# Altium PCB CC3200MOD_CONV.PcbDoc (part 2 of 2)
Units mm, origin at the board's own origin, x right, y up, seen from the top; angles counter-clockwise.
Board outline 40.99 x 49.89 mm, 2 copper layers (Top Layer, Bottom Layer), stack 1.071 mm thick; 81 components, 78 nets, 312 pads, 246 vias.
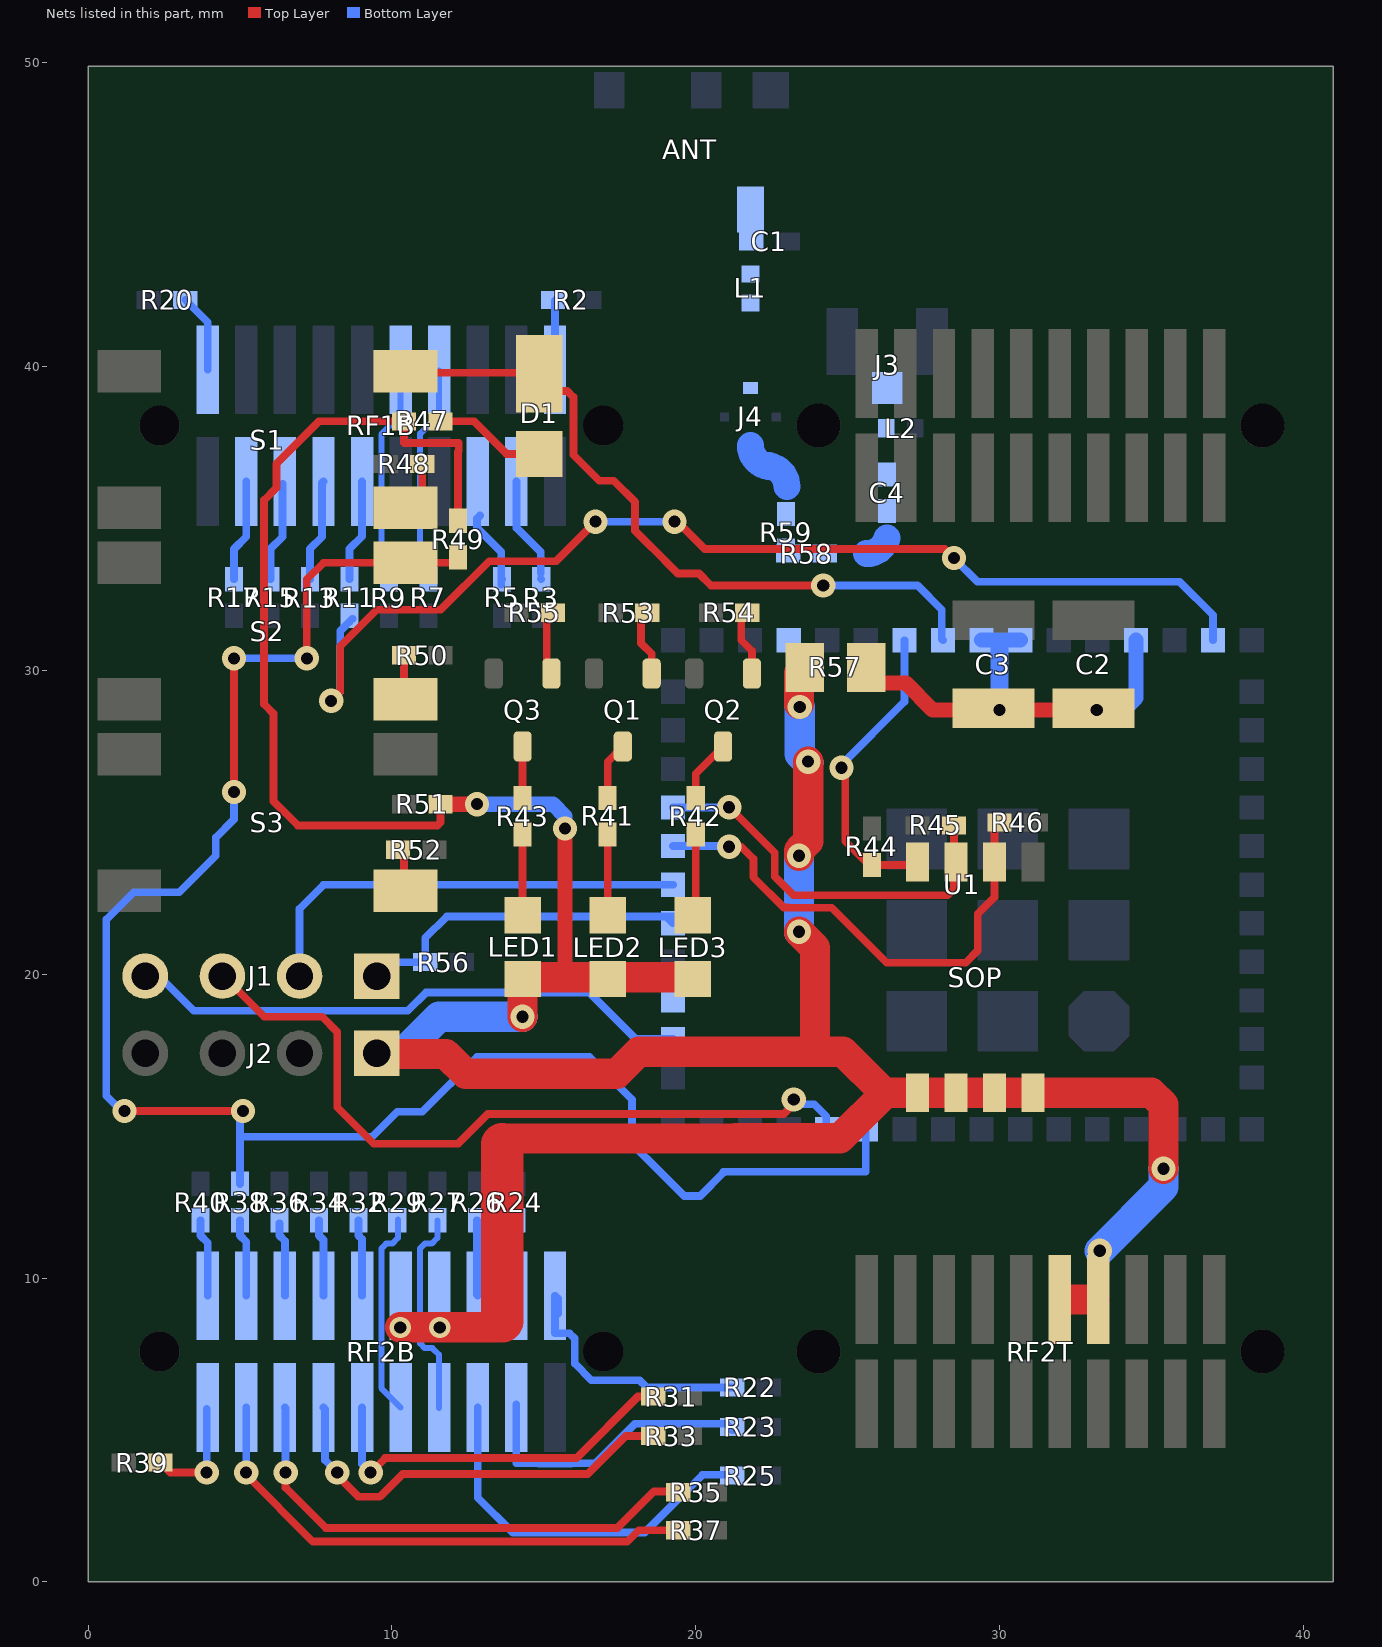
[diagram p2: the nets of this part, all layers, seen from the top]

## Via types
v1: diameter 0.8, hole 0.4, Top Layer to Bottom Layer, tented both sides, 237 vias
v2: diameter 1.27, hole 0.711, Top Layer to Bottom Layer, tented bottom, 7 vias
v3: diameter 0.7, hole 0.4, Top Layer to Bottom Layer, tented both sides, 2 vias

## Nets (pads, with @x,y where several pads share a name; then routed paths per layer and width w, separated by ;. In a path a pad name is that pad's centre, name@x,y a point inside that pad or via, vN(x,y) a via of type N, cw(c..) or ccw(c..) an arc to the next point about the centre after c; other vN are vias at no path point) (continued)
GPIO22: R38.2 R49.2 S2.2 U1.11 | length 60.4
  Top Layer w0.254: v1(1.2,15.5) v1(5.1,15.5) ; v1(4.8,26) v1(4.8,30.4) ; v1(7.2,30.4) 7.2,33 7.75,33.55 S2.2@10.45,33.55 R49.2@12.15,33.55
  Bottom Layer w0.254: v1@1.1,15.5 0.6,16 0.6,21.8 1.5,22.7 3,22.7 4.2,23.9 4.2,24.5 4.8,25.1 v1(4.8,26) ; v1(4.8,30.4) v1(7.2,30.4) ; R38.2@5,13.1 v1@5,15.5 ; 5,14.65 9.35,14.65 10.175,15.475 11,15.475 12.8,17.275 16.507,17.275 17.9,15.882 17.9,14.425 18.8,13.525 ; 18.791,13.534 19.625,12.7 20.149,12.7 20.913,13.463 20.913,13.5 25.6,13.5 U1.11@25.6,14.9
GPIO28: U1.19
GPIO30: R11.1 U1.42 | length 37.7
  Top Layer w0.254: v1(8,29) 8.3,29.3 8.3,30.8 9.5,32 11.6,32 13.2,33.6 15.4,33.6 v1(16.7,34.9) ; v1@19.35,34.95 20.3,34 28.2,34 v1(28.5,33.7)
  Bottom Layer w0.254: v1(8,29) 8.3,29.3 8.3,31.3 R11.1@8.7,31.7 ; v1(16.7,34.9) v1(19.3,34.9) ; v1(28.5,33.7) 29.275,32.925 35.924,32.925 37.03,31.819 U1.42@37.03,31 ; R11.1@8.7,31.7 8.6,31.6 R11.1@8.7,31.7
MCU_RXD: R9.2 RF1B.10 | length 7.3
  Bottom Layer w0.2: R9.2@9.9,33 9.9,33.7 9.65,33.95 9.65,37.775 10.287,38.412 RF1B.10@10.287,39.908
MCU_TXD: R7.2 RF1B.8 | length 7.2
  Bottom Layer w0.2: R7.2@11.2,33 11.2,33.75 10.925,34.025 10.925,37.8 11.55,38.425 RF1B.8@11.55,39.875
NetANT_3: ANT.3 C1.2 L1.2
NetC4_1: C4.1 R58.1 | length 0.9
  Bottom Layer w0.889: 25.625,33.85 ccw(c25.625,34.55) 26.298,34.357
NetC4_2: C4.2 J3.1 L2.2
NetD1_2: D1.2 R47.2 | length 3.9
  Top Layer w0.254: R47.2@11.6,38.2 12.7,38.2 13.775,37.125 D1.2@15.1,37.125
NetJ4_1: J4.1 R59.2 | length 2.2
  Bottom Layer w0.889: J4.1@21.8,37.41 ccw(c22.5,37.41) 22.5,36.71 ; 22.3,36.75 cw(c22.3,36.05) 23,36.05
NetJ4_2: J4.2 L1.1
NetLED1_2: LED1.2 R43.2 | length 2.7
  Top Layer w0.254: R43.2@14.3,24.6 14.3,21.95 LED1.2@14.305,21.945
NetLED2_2: LED2.2 R41.2 | length 2.7
  Top Layer w0.254: R41.2@17.1,24.6 17.1,21.95 LED2.2@17.105,21.945
NetLED3_2: LED3.2 R42.2 | length 2.7
  Top Layer w0.254: LED3.2@19.905,21.945 20,22.041 R42.2@20,24.6
NetQ1_1: Q1.1 R53.2 | length 4.1
  Top Layer w0.254: Q1.1@18.55,29.9 18.55,30.55 18.2,30.9 ; 18.2,30.9 R53.2@18.2,31.9 ; 18.2,30.9 R53.2@18.2,31.9 ; 18.2,30.9 R53.2@18.2,31.9
NetQ1_3: Q1.3 R41.1 | length 1.9
  Top Layer w0.254: R41.1@17.1,25.8 17.1,27 Q1.3@17.6,27.5
NetQ2_1: Q2.1 R54.2 | length 3
  Top Layer w0.254: Q2.1@21.85,29.9 21.85,30.65 21.5,31 ; 21.5,31 21.5,31.9 21.5,31
NetQ2_3: Q2.3 R42.1 | length 2.1
  Top Layer w0.254: R42.1@20,25.8 20,26.6 Q2.3@20.9,27.5
NetQ3_1: Q3.1 R55.2 | length 5.6
  Top Layer w0.254: Q3.1@15.1,30.05 R55.2@15.1,31.9 ; Q3.1@15.1,30.05 R55.2@15.1,31.9 ; Q3.1@15.1,30.05 R55.2@15.1,31.9
NetQ3_3: Q3.3 R43.1 | length 1.7
  Top Layer w0.254: R43.1@14.3,25.8 Q3.3@14.3,27.5
NetR2_2: R2.2 RF1B.2 | length 2.3
  Bottom Layer w0.254: RF1B.2@15.367,39.908 15.367,42.167 R2.2@15.4,42.2
NetR3_2: R3.2 RF1B.3 | length 3.4
  Bottom Layer w0.254: RF1B.3@14.097,36.225 14.1,36.222 14.1,34.7 ; 14.1,34.688 14.1,34.7 ; R3.2@14.897,33.021 R3.2@14.918,33 ; R3.2@14.901,33.202 14.899,33.901 14.1,34.7
NetR5_2: R5.2 RF1B.5 | length 2.9
  Bottom Layer w0.254: RF1B.5@12.9,35.1 12.8,35 12.8,34.7 13.6,33.9 13.6,32.827 13.6,33.027 R5.2@13.627,33
NetR11_2: R11.2 RF1B.11 | length 3.4
  Bottom Layer w0.254: R11.2@8.6,33 8.6,34 9.017,34.417 RF1B.11@9.017,36.225
NetR13_2: R13.2 RF1B.13 | length 3.4
  Bottom Layer w0.254: R13.2@7.3,33 7.3,34 7.7,34.4 7.7,36.178 RF1B.13@7.747,36.225
NetR15_2: R15.2 RF1B.15 | length 3.3
  Bottom Layer w0.254: R15.2@6,33 6,34 6.4,34.4 RF1B.15@6.4,36.148
NetR17_2: R17.2 RF1B.17 | length 3.4
  Bottom Layer w0.254: R17.2@4.8,33 4.8,34 5.207,34.407 RF1B.17@5.207,36.225
NetR20_2: R20.2 RF1B.20 | length 2.6
  Bottom Layer w0.254: R20.2@3.2,42.2 3.937,41.463 RF1B.20@3.937,39.908
NetR22_2: R22.2 RF2B.2 | length 8.8
  Bottom Layer w0.254: RF2B.2@15.367,9.422 15.367,8.183 15.842,8.183 16.015,8.01 16.015,7.191 16.565,6.64 18.148,6.64 18.389,6.4 R22.2@21.2,6.4 ; RF2B.2@15.464,8.836 RF2B.2@15.464,9.325
NetR23_2: R23.2 RF2B.3 | length 9.7
  Bottom Layer w0.254: RF2B.3@14.097,5.839 14.097,3.903 14.1,3.9 14.838,3.9 14.841,3.897 15.893,3.897 15.896,3.9 16.7,3.9 18,5.2 21,5.2 R23.2@21.2,5
NetR24_1: R24.1 RF2B.4 | length 2.5
  Bottom Layer w0.254: RF2B.4@14.097,9.422 14.1,9.425 R24.1@14.1,11.9
NetR25_2: R25.2 RF2B.5 | length 12.4
  Bottom Layer w0.254: RF2B.5@12.827,5.739 12.827,2.773 13.975,1.625 18.325,1.625 20.225,3.525 R25.2@21.025,3.525
NetR26_1: R26.1 RF2B.6 | length 2.5
  Bottom Layer w0.254: R26.1@12.8,11.9 12.8,9.448 RF2B.6@12.827,9.422
NetR27_2: R27.2 RF2B.7 | length 7
  Bottom Layer w0.2: R27.2@11.5,11.9 11.5,11.325 11.309,11.134 11.084,11.134 10.925,10.975 10.925,7.85 11.081,7.694 11.331,7.694 11.55,7.475 RF2B.7@11.55,5.725
NetR29_2: R29.2 RF2B.9 | length 6.8
  Bottom Layer w0.2: R29.2@10.2,11.925 10.2,11.325 10.009,11.134 9.814,11.134 9.65,10.97 9.65,6.376 RF2B.9@10.287,5.739
NetR31_2: R31.2 RF2B.11 | length 12.6
  Top Layer w0.254: v1(9.3,3.6) 9.775,4.075 16.075,4.075 18.1,6.1 R31.2@18.6,6.1
  Bottom Layer w0.254: RF2B.11@9.017,5.739 9.017,3.883 v1(9.3,3.6)
NetR32_1: R32.1 RF2B.12 | length 2.5
  Bottom Layer w0.254: R32.1@8.9,11.9 8.9,11.4 9.017,11.283 RF2B.12@9.017,9.422
NetR33_2: R33.2 RF2B.13 | length 14.1
  Top Layer w0.254: v1@8.3,3.6 v1(8.2,3.6) 8.2,3.5 8.9,2.8 9.6,2.8 9.619,2.819 9.624,2.819 10.355,3.55 16.45,3.55 17.7,4.8 R33.2@18.6,4.8
  Bottom Layer w0.254: RF2B.13@7.747,5.739 7.8,5.685 7.8,4 v1(8.2,3.6) v1@8.3,3.6
NetR34_1: R34.1 RF2B.14 | length 2.5
  Bottom Layer w0.254: R34.1@7.6,11.9 7.6,11.4 7.747,11.253 RF2B.14@7.747,9.422
NetR35_2: R35.2 RF2B.15 | length 17.1
  Top Layer w0.254: v1@6.3,3.6 v1(6.5,3.6) 6.5,3.1 7.825,1.775 17.425,1.775 18.625,2.975 R35.2@19.5,2.975
  Bottom Layer w0.254: v1@6.3,3.6 v1(6.5,3.6) 6.5,5.716 RF2B.15@6.477,5.739
NetR36_1: R36.1 RF2B.16 | length 2.5
  Bottom Layer w0.254: R36.1@6.3,11.8 6.3,11.4 6.477,11.223 RF2B.16@6.477,9.422
NetR37_2: R37.2 RF2B.17 | length 17.5
  Top Layer w0.254: v1(5.2,3.6) 5.2,3.525 7.4,1.325 17.75,1.325 18.125,1.7 R37.2@19.4,1.7
  Bottom Layer w0.254: v1(5.2,3.6) 5.2,5.732 RF2B.17@5.207,5.739
NetR38_1: R38.1 RF2B.18 | length 2.6
  Bottom Layer w0.254: R38.1@5,11.9 5,11.4 5.207,11.193 RF2B.18@5.207,9.422
NetR39_2: R39.2 RF2B.19 | length 3.8
  Top Layer w0.254: R39.2@2.375,3.925 2.7,3.6 v1(3.9,3.6)
  Bottom Layer w0.254: v1(3.9,3.6) RF2B.19@3.9,5.701
NetR40_1: R40.1 RF2B.20 | length 2.6
  Bottom Layer w0.254: R40.1@3.7,11.9 3.7,11.4 3.937,11.163 RF2B.20@3.937,9.422
NetR48_1: R48.1 S1.4 | length 1.9
  Top Layer w0.254: S1.4@10.4,35.6 S1.4@10.55,35.45 ; S1.4@10.45,35.35 S1.4@10.55,35.45 ; R48.1@11,36.8 11,35.9 S1.4@10.55,35.45
NetR50_1: R50.1 S2.4 | length 2.3
  Top Layer w0.254: R50.1@10.4,30.5 S2.4@10.4,29.3 ; S2.4@10.4,29.3 10.55,29.15 S2.4@10.65,29.05 ; S2.4@10.4,29.3 S2.4@10.65,29.05 ; S2.4@10.4,29.3 S2.4@10.65,29.05
NetR52_1: R52.1 S3.4 | length 2.2
  Top Layer w0.254: R52.1@10.4,24.1 S3.4@10.4,23 ; S3.4@10.4,23 10.55,22.85 S3.4@10.65,22.75 ; S3.4@10.4,23 S3.4@10.65,22.75 ; S3.4@10.4,23 S3.4@10.65,22.75
NRESET: D1.1 S1.2 U1.35 | length 23.7
  Top Layer w0.254: S1.2@10.65,39.85 10.7,39.8 14.625,39.8 D1.1@14.754,39.671 ; D1.1@14.85,39.767 15.417,39.2 15.775,39.2 15.975,39 15.975,37.1 16.825,36.25 17.3,36.25 18,35.55 18,34.6 18.543,34.057 ; 18.5,34.1 19.408,33.192 20.108,33.192 20.5,32.8 24.4,32.8 24.4,32.6 v1(24.2,32.8)
  Bottom Layer w0.254: 24.6,32.8 27.3,32.8 28.1,32 28.1,31.04 U1.35@28.14,31
RF_BG: R58.2 R59.1 U1.31
SOP0: R44.2 SOP.8 U1.34 | length 10.2
  Top Layer w0.254: v1@24.8,26.6 24.925,26.475 24.925,24.375 25.7,23.6 26.1,23.6 ; R44.2@26,23.6 27.2,23.6 SOP.8@27.295,23.695
  Bottom Layer w0.254: v1(24.8,26.8) 24.8,26.9 26.87,28.97 U1.34@26.87,31
SOP1: R45.2 SOP.7 U1.24 | length 13.2
  Top Layer w0.254: v1(21.1,25.5) 22.6,24 22.6,23.218 23.218,22.6 28.3,22.6 28.5,22.8 R45.2@28.5,25
  Bottom Layer w0.254: U1.24@19.25,25.49 v1@21.09,25.49
SOP2: R46.2 SOP.6 U1.23 | length 16.6
  Top Layer w0.254: v1(21.1,24.2) 21.5,24.2 21.9,23.8 21.9,23.2 22.9,22.2 23.044,22.2 23.05,22.194 24.474,22.194 26.284,20.384 28.884,20.384 29.284,20.784 29.284,21.984 29.835,22.535 SOP.6@29.835,23.695 29.835,24.965 R46.2@29.8,25
  Bottom Layer w0.254: U1.23@19.25,24.22 v1@21.08,24.22
TCK: J1.1 R56.2 U1.21 | length 11.7
  Bottom Layer w0.254: J1.1@9.5,20.4 R56.2@11.1,20.4 11.1,21.2 11.8,21.9 U1.21@19.3,21.9 ; U1.21@19.25,21.68 U1.21@19.03,21.9 ; U1.21@19.03,21.9 19.25,21.9 U1.21@19.3,21.9 ; U1.21@19.03,21.9 U1.21@19.3,21.9
TDI: J1.3 U1.12 | length 25.5
  Top Layer w0.254: J1.3@4.42,20.4 4.42,19.98 5.8,18.6 7.7,18.6 8.2,18.1 8.2,15.625 9.4,14.425 12.175,14.425 13.15,15.4 22.9,15.4 23.225,15.725 v1(23.225,15.875)
  Bottom Layer w0.254: v1(23.225,15.875) 23.375,15.725 23.9,15.725 24.3,15.325 U1.12@24.3,14.93 ; U1.12@24.3,15 U1.12@24.3,14.93 ; U1.12@24.33,14.9 U1.12@24.3,14.93
TDO: J1.4 U1.18 | length 18.9
  Bottom Layer w0.254: J1.4@1.88,20.4 3.48,18.8 10.525,18.8 11.125,19.4 16.5,19.4 18.03,17.87 U1.18@19.25,17.87
TMS: J1.2 U1.22 | length 16.1
  Bottom Layer w0.254: U1.22@19.25,22.95 7.75,22.95 6.96,22.16 ; 6.96,22.16 6.96,20.4 6.96,22.16
VCC: C2.1 C3.1 R57.2 U1.36 U1.37 U1.40 | length 16.8
  Top Layer w0.5: R57.2@25.5,29.584 26.916,29.584 27.8,28.7 v1(30,28.7) ; 28.1,28.7 v1(30,28.7) ; v1(33.2,28.7) v1(30,28.7)
  Bottom Layer w0.5: U1.36@29.41,31 U1.37@30.68,31 ; v1(33.2,28.7) 34.1,28.7 34.49,29.09 U1.40@34.49,31
  Bottom Layer w0.58: v1(30,28.7) 30,30.95
VCC_BRD: J2.1 LED1.1 LED2.1 LED3.1 R47.1 R49.1 R51.1 R57.1 RF2B.8 RF2B.10 RF2T.7 RF2T.9 SOP.1 SOP.2 SOP.3 SOP.4 | length 118.5
  Top Layer w0.254: R51.1@11.6,25.6 11.6,25 11.5,24.9 6.9,24.9 6.1,25.7 6.1,28.582 5.792,28.89 5.792,35.61 6.2,36.018 6.2,36.8 7.6,38.2 R47.1@10.4,38.2 10.4,37.5 10.409,37.491 12.2,37.491 12.2,37.225 12.175,37.2 12.175,36.205 R49.1@12.175,34.925 ; LED1.1@14.3,19.841 LED1.1@14.305,19.845 LED1.1@14.359,19.9 ; LED2.1@17.05,19.9 LED2.1@17.105,19.845 ; LED3.1@19.85,19.9 LED3.1@19.905,19.845 LED3.1@19.959,19.9
  Top Layer w0.5: J2.1@9.5,17.35 J2.1@9.525,17.375 ; R51.1@11.6,25.6 v1(12.8,25.6) ; 15.7,19.9 v1(15.7,24.8)
  Top Layer w1: J2.1@9.525,17.375 11.775,17.375 12.425,16.725 17.4,16.725 18.125,17.45 24.85,17.45 26.2,16.1 32.9,16.1 ; v3(10.275,8.375) v3(11.575,8.375) 13.425,8.375 13.625,8.575 ; 13.625,14.4 13.821,14.596 ; 13.721,14.596 21.306,14.596 21.311,14.6 24.75,14.6 26.25,16.1 ; v1(14.3,18.6) LED1.1@14.3,19.841 ; LED1.1@14.359,19.9 15.7,19.9 LED2.1@17.05,19.9 ; LED2.1@17.505,19.9 LED3.1@19.85,19.9 ; v1(23.4,21.4) 23.925,20.875 23.925,17.5 ; v1(23.4,23.9) 23.4,24.075 23.7,24.375 v1(23.7,27) ; v1@23.4,28.9 R57.1@23.4,29.916 ; RF2T.9@32.125,9.295 RF2T.7@33.125,9.295 ; 33,16.1 35,16.1 35.4,15.7 v1(35.4,13.6)
  Top Layer w1.4: 13.625,8.575 13.625,14.4
  Bottom Layer w0.254: v1@23.7,26.95 v1(23.7,27)
  Bottom Layer w0.5: v1(12.8,25.6) 15.3,25.6 15.7,25.2 v1(15.7,24.8)
  Bottom Layer w1: J2.1@9.525,17.425 9.575,17.375 10.325,17.375 11.55,18.6 v1(14.3,18.6) ; v1(23.4,21.4) v1(23.4,23.9) ; v1(23.425,28.8) 23.425,27.25 v1@23.7,26.975 ; v1(33.3,10.9) 35.4,13 v1(35.4,13.6)
pads on no net: Logo1.0 R3.1 R5.1 R13.1 R15.1 R17.1 R36.2 RF1B.1 RF1B.4 RF1B.6 RF1B.7 RF1B.9 RF1B.12 RF1B.14 RF1B.16 RF1B.18 RF1B.19 RF1B.21 RF1B.22 RF1T. RF1T.2 RF1T.3 RF1T.4 RF1T.5 RF1T.6 RF1T.8 RF1T.10 RF1T.11 RF1T.12 RF1T.13 RF1T.14 RF1T.15 RF1T.16 RF1T.17 RF1T.18 RF1T.20 RF2B.21 RF2B.22 RF2T. RF2T.1 RF2T.3 RF2T.4 RF2T.5 RF2T.6 RF2T.8 RF2T.10 RF2T.11 RF2T.12 RF2T.13 RF2T.14 RF2T.15 RF2T.16 RF2T.17 RF2T.18 RF2T.19 S1.1 S1.3 S2.1 S2.3 S3.1 S3.3 U1.13 U1.14 U1.15 U1.17 U1.20 U1.25 U1.26 U1.29 U1.33 U1.39 U1.41 U1.45

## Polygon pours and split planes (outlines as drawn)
DGND on Top Layer "Top Layer-No Net" (solid, remove dead copper, pour order 6): 0,49.9 41,49.9 41,0 0,0 0,49.9
DGND on Bottom Layer "Bottom Layer-No Net" (solid, remove dead copper, pour order 10): 40.998,49.843 -0.002,49.843 -0.002,0.043 40.998,0.043 40.998,49.843

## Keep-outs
Keep-Out Layer:
  lines w0.254: -0.127,50.021 -0.127,0 ; 0,50.021 41.115,50.021 41.115,-0.127 0,-0.127 ; -0.127,0 ccw(c0,0) 0,-0.127 ; -0.127,0 ccw(c0,0) 0,-0.127 ; -0.127,0 ccw(c0,0) 0,-0.127 ; -0.127,0 ccw(c0,0) 0,-0.127 ; -0.127,0 ccw(c0,0) 0,-0.127 ; -0.127,0 ccw(c0,0) 0,-0.127 ; 116.53,78.957 cw(c116.53,78.83) 116.657,78.83 ; 116.53,78.957 cw(c116.53,78.83) 116.657,78.83 ; 116.53,78.957 cw(c116.53,78.83) 116.657,78.83 ; 116.53,78.957 cw(c116.53,78.83) 116.657,78.83 ; 116.53,78.957 cw(c116.53,78.83) 116.657,78.83 ; 116.53,78.957 cw(c116.53,78.83) 116.657,78.83
  text ".Layer_Name" at 14.656,-21.806 h1.52

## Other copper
Top Layer:
  text ".PRJ_Number" at 41.75,39.33 h1
  text ".Layer_Name" at 14.656,-21.806 h1.52
Bottom Layer:
  rectangle net NetJ4_2: 21.35,39.1 22.25,42.375
  rectangle net NetC4_1: 25.85,34.4 26.75,35.65
  region net NetC4_1: 25.625,33.406 25.625,34.295 23.762,34.295 23.762,33.406
  rectangle net NetC4_2: 25.85,36.05 26.75,39.8
  rectangle net NetANT_3: 21.35,42.775 22.25,45.925
  rectangle net NetJ4_1: 22.55,34.75 23.45,36.1
  rectangle net NetC4_1: 25.85,35.5 26.75,39.25
  rectangle net RF_BG: 22.55,30.6 23.45,34.525
  text ".PRJ_Number" at 41.75,37.457 h1
  text ".VersionControl_RevNumber" at 98.831,4.559 h1.52
  text "SVN:" at 105.918,4.559 h1.52
  text ".Layer_Name" at 14.656,-21.806 h1.52

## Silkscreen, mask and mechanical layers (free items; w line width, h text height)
Top Overlay:
  text ".PRJ_Number" at 41.75,44.95 h1
  text "SOP0" at 27,14.3 h0.8 r270
  text "SOP1" at 28.2,14.3 h0.8 r270
  text "SOP2" at 29.5,14.3 h0.8 r270
  text "MODE" at 30.8,14.3 h0.8 r270
  text "J1:" at 3.5,6.2 h0.8
  text "TDO" at 5.6,6.2 h0.8
  text "TDI" at 8.1,6.2 h0.8
  text "TMS" at 10.6,6.2 h0.8
  text "TCK" at 13.2,6.2 h0.8
  text "J2:" at 3.4,4.5 h0.8
  text "VSS" at 5.575,4.3 h0.8
  text "TXD" at 8.075,4.3 h0.8
  text "RXD" at 10.675,4.3 h0.8
  text "VDD" at 13.2,4.3 h0.8
  text "©" at 25,1.1 h2.67
  text ".CopyrightYear" at 27.39,1.1 h1.52
  text "TI" at 36.1,1.1 h1.52
  text ".Layer_Name" at 14.656,-21.806 h1.52
Bottom Overlay:
  text "*" at 16.025,40.425 h1.02
  text ".PRJ_Number" at 41.75,31.837 h1
  text "UL94V-0" at 14.575,23.3 h1.52
  text "*" at 16.05,10 h1.02
  text ".PCB_Rev" at 20.55,9.475 h1
  text ".PRJ_Number" at 40.6,9.425 h1
  text ".Layer_Name" at 14.656,-21.806 h1.52
Top Paste:
  text ".PRJ_Number" at 41.75,41.204 h1
  text ".Layer_Name" at 14.656,-21.806 h1.52
Bottom Paste:
  text ".PRJ_Number" at 41.75,35.584 h1
  text ".Layer_Name" at 14.656,-21.806 h1.52
Top Solder:
  text ".PRJ_Number" at 41.75,43.077 h1
  text ".Layer_Name" at 14.656,-21.806 h1.52
  text ".Layer_Name" at 14.656,-21.806 h1.52
Bottom Solder:
  text ".PRJ_Number" at 41.75,33.711 h1
  text ".Layer_Name" at 14.656,-21.806 h1.52
Drill Guide:
  text ".PRJ_Number" at 41.75,22.471 h1
  text ".Layer_Name" at 14.656,-21.806 h1.52
M1 Board Outline:
  lines w0.254: 40.988,10 40.988,0 0,0 0,49.894 40.988,49.894 40.988,10.012
  text ".PRJ_Number" at 41.75,29.964 h1
  text ".Layer_Name" at 14.656,-21.806 h1.52
M2 Board Dimensions:
  rectangle: 0,-7.252 3.175,-4.077
  rectangle: 3.175,-10.427 12.7,-7.252
  lines w0.178: 0,-7.252 25.4,-7.252 ; 3.175,-10.427 3.175,-4.077 ; 6.35,-10.427 6.35,-4.077 ; 12.7,-10.427 12.7,-4.077 ; 19.05,-10.427 19.05,-4.077 ; 0,-10.427 25.4,-10.427 25.4,-4.077 0,-4.077 0,-10.427
  text ".PRJ_Number" at 41.75,28.091 h1
  text ".Layer_Name" at 14.656,-21.806 h1.52
M3 3D STEP Top:
  text ".Layer_Name" at 14.656,-21.806 h1.52
M4 3D STEP Bottom:
  text ".Layer_Name" at 14.656,-21.806 h1.52
M5 Assembly Top:
  lines w0.254: -7.417,-23.626 160.223,-23.626 ; -7.417,-18.462 160.274,-18.462 ; -7.417,-13.297 -7.417,-28.791 94.31,-28.791 160.274,-28.791 160.274,-13.297 -7.404,-13.297 -7.404,-28.791 32.614,-28.791 ; 55.194,-28.791 55.194,-13.297 ; 87.376,-18.462 87.376,-13.297 ; 108.712,-18.462 108.712,-13.297 ; 124.511,-28.956 124.511,-23.804
  text ".PRJ_Number" at 41.75,26.218 h1
  text "COMPONENTS MARKED 'DNP' SHOULD NOT BE POPULATED." at 29.299,-8.09 h1.52
  text "ASSEMBLY VARIANT:" at 29.286,-11.024 h1.52
  text ".VariantName" at 55.601,-11.024 h1.52
  text "PCB VIEWED FROM TOP SIDE" at -5.804,-16.654 h1.52
  text "BOARD #:" at 57.099,-16.654 h1.52
  text ".PRJ_Number" at 70.955,-16.654 h1.52
  text "REV:" at 92.405,-16.654 h1.52
  text ".PCB_Rev" at 99.809,-16.654 h1.52
  text "SVN REV:" at 113.69,-16.654 h1.52
  text ".VersionControl_RevNumber" at 126.543,-16.654 h1.52
  text "IGNORE ->" at -5.804,-21.806 h1.52
  text "PLOT NAME =" at -5.804,-27.034 h1.52
  text ".plot_File_Name" at 14.656,-27.034 h1.52
  text "GENERATED    :" at 57.15,-27.034 h1.52
  text ".Print_Date" at 79.235,-27.034 h1.52
  text ".Print_Time" at 97.752,-27.034 h1.52
  text "TEXAS INSTRUMENTS" at 129.87,-27.034 h1.52
M6 Assembly Bottom:
  lines w0.254: -7.429,-18.474 160.261,-18.474 ; -7.379,-23.639 160.261,-23.639 ; 28.334,-28.969 28.334,-23.817 ; 44.133,-18.474 44.133,-13.31 ; 65.468,-18.474 65.468,-13.31 ; 97.65,-28.804 97.65,-13.31 ; 120.231,-28.804 160.249,-28.804 160.249,-13.31 -7.429,-13.31 -7.429,-28.804 58.534,-28.804 160.261,-28.804 160.261,-13.31
  text ".PRJ_Number" at 41.75,24.345 h1
  text "COMPONENTS MARKED 'DNP' SHOULD NOT BE POPULATED." at 154.991,-8.077 h1.52
  text ".VariantName" at 128.473,-11.024 h1.52
  text "ASSEMBLY VARIANT:" at 154.864,-11.024 h1.52
  text ".VersionControl_RevNumber" at 26.302,-16.667 h1.52
  text "SVN REV:" at 39.154,-16.667 h1.52
  text ".PCB_Rev" at 53.035,-16.667 h1.52
  text "REV:" at 60.439,-16.667 h1.52
  text ".PRJ_Number" at 81.89,-16.667 h1.52
  text "BOARD #:" at 95.745,-16.667 h1.52
  text "PCB VIEWED FROM BOTTOM SIDE" at 158.648,-16.667 h1.52
  text "IGNORE ->" at 64.715,-21.806 h1.52
  text "TEXAS INSTRUMENTS" at 22.974,-27.047 h1.52
  text ".Print_Time" at 55.093,-27.047 h1.52
  text ".Print_Date" at 73.609,-27.047 h1.52
  text "GENERATED    :" at 95.694,-27.047 h1.52
  text ".plot_File_Name" at 138.189,-27.047 h1.52
  text "PLOT NAME =" at 158.648,-27.047 h1.52
M9 Title Sheet:
  drawing of 57 lines, arcs and shapes, not listed
  text "1" at 18.792,204.127 h1.78
  text "2" at 82.182,204.127 h1.78
  text "3" at 145.411,204.127 h1.78
  text "4" at 209.08,204.127 h1.78
  text "5" at 272.555,204.127 h1.78
  text "6" at 336.182,204.127 h1.78
  text "A" at -10.579,175.095 h1.78
  text "A" at 365.341,175.095 h1.78
  text "B" at -10.579,114.643 h1.78
  text "B" at 365.341,114.643 h1.78
  text "C" at -10.579,54.318 h1.78
  text "C" at 365.341,54.318 h1.78
  text "PROJECT TITLE:" at 288.125,7.048 h1.14
  text ".PRJ_Title" at 289.395,3.662 h1.78
  text "DESIGNED FOR:" at 288.125,-0.597 h1.14
  text ".PRJ_Customer" at 289.395,-4.153 h1.78
  text "D" at -10.579,-5.88 h1.78
  text "D" at 365.341,-5.88 h1.78
  text "FILE NAME:" at 288.125,-8.217 h1.14
  text ".PCB_File_Name_No_Path" at 289.395,-11.265 h1.78
  text "Texas Instruments (TI) and/or its licensors do not warrant the accuracy or completeness of this specification" at 161.9,-15.376 h1.14
  text "ENGINEER:" at 288.125,-15.583 h1.14
  text "LAYOUT BY:" at 326.352,-15.583 h1.14
  text "or any information contained therein. TI and/or its licensors do not warrant that this design will meet" at 160.757,-18.237 h1.14
  text ".PRJ_Engineer" at 289.395,-19.52 h1.78
  text ".PCB_Layout" at 327.635,-19.52 h1.78
  text "the specifications, will be suitable for your application or fit for any particular purpose, or will operate in" at 160.757,-21.099 h1.14
  text ".Layer_Name" at 14.656,-21.806 h1.52
  text "ALTIUM DESIGNER VERSION:" at 326.352,-23.457 h1.14
  text "an implementation. TI and/or its licensors do not warrant that the design is production worthy. You should" at 160.757,-23.961 h1.14
  text "completely validate and test your design implementation to confirm the system functionality for your application." at 161.9,-26.822 h1.14
  text ".print_Scale" at 289.395,-26.843 h1.78
  text ".Application_BuildNumber" at 327.635,-26.843 h1.78
  text "1" at 18.792,-32.093 h1.78
  text "2" at 82.182,-32.093 h1.78
  text "3" at 145.411,-32.093 h1.78
  text "4" at 209.08,-32.093 h1.78
  text "5" at 272.555,-32.093 h1.78
  text "6" at 336.182,-32.093 h1.78
M10 Fab Notes:
  drawing of 185 lines, arcs and shapes, not listed
  text "DESIGN INFORMATION" at 314.478,150.114 h1.52
  text "MIN. TRACK WIDTH:" at 298.106,145.542 h1.52
  text "8" at 325.951,145.542 h1.52
  text "MIL" at 329.881,145.542 h1.52
  text "MIN. CLEARANCE:" at 298.106,142.189 h1.52
  text "0.2" at 324.427,142.189 h1.52
  text "mm" at 329.881,142.189 h1.52
  text "MIN. VIA PAD SIZE:" at 298.106,138.836 h1.52
  text "24" at 325.189,138.836 h1.52
  text "MIL" at 329.881,138.836 h1.52
  text "0.05mm (2MIL)" at 315.759,135.237 h1.52
  text "MINIMUM ANNULAR RING" at 289.744,135.128 h1.52
  text "EXTERNAL" at 333.742,135.128 h1.52
  text "PER" at 294.824,132.131 h1.52
  text "IPC-D-275 CLASS 2 LEVEL C" at 300.412,132.131 h1.52
  text "MIL, HOLES" at 338.213,129.279 h1.52
  text "+/-" at 328.244,129.261 h1.52
  text "+/-" at 349.936,129.261 h1.52
  text "REGISTRATION TOLERANCES:" at 289.744,129.134 h1.52
  text "METAL" at 320.218,129.134 h1.52
  text "5" at 334.853,129.134 h1.52
  text "3" at 356.012,129.134 h1.52
  text "MIL" at 358.964,129.134 h1.52
  text "MATERIAL:" at 287.844,123.813 h1.52
  text "FR-4 High Tg" at 312.9,120.249 h1.52
  text "FR-408" at 298.538,120.031 h1.52
  text "X" at 309.003,120.031 h1.52
  text "OTHER" at 336.333,120.031 h1.52
  text "62 MIL (1.6mm) +/-10%" at 306.668,115.898 h1.52
  text "THICKNESS:" at 289.744,115.789 h1.52
  text "X" at 303.413,115.789 h1.52
  text "OTHER" at 339.305,115.789 h1.52
  text "TOLERANCE:" at 289.744,111.776 h1.52
  text "X" at 311.062,111.776 h1.52
  text "ANSI IPC-6012 TYPE 3 CLASS 2" at 315.81,111.776 h1.52
  text "OTHER +/-" at 315.81,107.814 h1.52
  text "BOW & TWIST:" at 289.744,103.826 h1.52
  text "X" at 311.062,103.826 h1.52
  text "ANSI IPC-6012 TYPE 3 CLASS 2" at 315.81,103.826 h1.52
  text "OTHER +/-" at 315.81,99.8 h1.52
  text "DRILLING:" at 287.844,96.282 h1.52
  text "REFERENCE:" at 289.744,93.31 h1.52
  text "X" at 306.209,93.31 h1.52
  text "AS SHOWN" at 310.958,93.31 h1.52
  text "X" at 329.094,93.31 h1.52
  text "NC_DRILL FILES" at 332.574,93.31 h1.52
  text "PTH MIN COPPER THICKNESS:" at 289.744,89.297 h1.52
  text "X" at 324.039,89.297 h1.52
  text "1MIL" at 327.519,89.297 h1.52
  text "OTHER" at 340.143,89.297 h1.52
  text "BOARD FINISH:" at 287.844,85.259 h1.52
  text "SILKSCREEN:" at 291.787,82.261 h1.52
  text "X" at 315.886,82.261 h1.52
  text "TOP" at 319.086,82.261 h1.52
  text "X" at 328.84,82.261 h1.52
  text "BOTTOM" at 332.066,82.261 h1.52
  text "SILKSCREEN COLOR:" at 291.787,78.02 h1.52
  text "X" at 315.86,78.02 h1.52
  text "WHITE" at 319.086,78.02 h1.52
  text "OTHER" at 332.066,78.02 h1.52
  text "SOLDER RESIST COLOR:" at 291.787,73.702 h1.52
  text "X" at 306.208,69.658 h1.52
  text "GREEN" at 309.434,69.658 h1.52
  text "BLUE" at 324.446,69.658 h1.52
  text "OTHER" at 338.111,69.658 h1.52
  text "IMMERSION GOLD (ENIG)" at 314.794,64.87 h1.52
  text "ENEPIG" at 348.767,64.786 h1.52
  text "SURFACE FINISH:" at 287.844,64.761 h1.52
  text "X" at 310.045,64.761 h1.52
  text "IMM. TIN/SILVER OR EQUIV" at 296.215,60.773 h1.52
  text "OTHER" at 332.574,60.773 h1.52
  text "ARRAY/PANEL:" at 287.844,56.226 h1.52
  text "CUT AND TRIM PER MECH LAYER 1" at 314.794,56.118 h1.52
  text "N.C. ROUTE" at 314.794,52.264 h1.52
  text "X" at 332.04,52.264 h1.52
  text "V. SCORE" at 336.79,52.264 h1.52
  text "CERTIFICATION:" at 287.844,48.784 h1.52
  text "MATERIALS AND WORKMANSHIP FOR ALL PCBS" at 306.259,48.784 h1.52
  text "TO MEET OR EXCEED THE REQUIREMENTS OF:" at 306.259,46.295 h1.52
  text "X" at 296.773,42.828 h1.52
  text "ANSI IPC-A-600F CLASS ->" at 300.303,42.828 h1.52
  text "X" at 341.935,42.828 h1.52
  text "2" at 344.956,42.828 h1.52
  text "1" at 336.955,42.79 h1.52
  text "3" at 353.948,42.79 h1.52
  text "X" at 296.825,38.777 h1.52
  text "UL 94V-0" at 300.303,38.777 h1.52
  text "X" at 317.45,38.777 h1.52
  text "RoHS" at 320.928,38.777 h1.52
  text "OTHER" at 337.296,38.777 h1.52
  text "PER ORDER" at 347.381,38.777 h1.52
  text "ADDITIONAL REQUIREMENTS:" at 287.844,35.195 h1.52
  text "MICROSECTION:" at 289.744,32.274 h1.52
  text "YES" at 312.749,32.274 h1.52
  text "REQUIRED" at 334.631,28.308 h1.52
  text "BARE BOARD ELEC. TEST:" at 289.744,28.236 h1.52
  text "NONE" at 322.909,28.236 h1.52
  text "X" at 331.405,28.236 h1.52
  text "PER ORDER" at 349.668,28.236 h1.52
  text "MANUFACTURER'S UL:" at 289.744,24.248 h1.52
  text "RAIL" at 319.353,24.139 h1.52
  text "METAL" at 331.845,24.139 h1.52
  text "X" at 341.376,24.13 h1.52
  text "SILK" at 344.842,24.139 h1.52
  text ".Layer_Name" at 14.656,-21.806 h1.52
M11 Gerber Information:
  lines w0.254: -7.417,-23.626 160.223,-23.626 ; -7.417,-18.462 160.274,-18.462 ; -7.417,-13.297 -7.417,-28.791 94.31,-28.791 160.274,-28.791 160.274,-13.297 -7.404,-13.297 -7.404,-28.791 32.614,-28.791 ; 55.194,-28.791 55.194,-13.297 ; 87.376,-18.462 87.376,-13.297 ; 108.712,-18.462 108.712,-13.297 ; 124.511,-28.956 124.511,-23.804
  text "ALL ARTWORK VIEWED FROM TOP SIDE" at -5.804,-16.654 h1.52
  text "BOARD #:" at 57.099,-16.654 h1.52
  text ".PRJ_Number" at 70.955,-16.654 h1.52
  text "REV:" at 92.405,-16.654 h1.52
  text ".PCB_Rev" at 99.809,-16.654 h1.52
  text "SVN REV:" at 113.69,-16.654 h1.52
  text ".VersionControl_RevNumber" at 126.543,-16.654 h1.52
  text "LAYER NAME =" at -5.804,-21.806 h1.52
  text "PLOT NAME =" at -5.804,-27.034 h1.52
  text ".plot_File_Name" at 14.656,-27.034 h1.52
  text "GENERATED    :" at 57.15,-27.034 h1.52
  text ".Print_Date" at 79.235,-27.034 h1.52
  text ".Print_Time" at 97.752,-27.034 h1.52
  text "TEXAS INSTRUMENTS" at 129.87,-27.034 h1.52
M12 Stackup:
  lines w0.152: 288.544,189.484 353.314,189.484 ; 288.544,192.136 353.314,192.136 ; 287.02,177.165 ccw(c287.884,177.165) 287.884,176.301 353.974,176.301 ccw(c353.974,177.165) 354.838,177.165 354.838,195.097 ccw(c353.974,195.097) 353.974,195.961 287.884,195.961 ccw(c287.884,195.097) 287.02,195.097 287.02,177.165
  text "The Stackup Legend below this is static." at 294.78,200.012 h1.52
  text "If you change the stackup, update the Legend." at 295.034,197.726 h1.52
  text "Layer Stack Up Detail for: Ref_Design.PcbDoc" at 288.544,192.966 h1.45
  text "Layer" at 288.544,191.145 h0.61
  text "Gerber" at 311.298,191.145 h0.61
  text "Copper" at 325.611,191.145 h0.61
  text "Dielectric" at 340.92,191.145 h0.61
  text "Name" at 288.544,189.926 h0.61
  text "Document" at 311.298,189.926 h0.61
  text "Thickness" at 325.611,189.926 h0.61
  text "Material" at 340.92,189.926 h0.61
  text "Top Solder Mask" at 288.544,187.565 h0.86
  text "(.GTS)" at 311.298,187.565 h0.86
  text "Solder Resist" at 340.92,187.565 h0.86
  text "Top Layer" at 288.544,185.107 h0.86
  text "(.GTL)" at 311.298,185.107 h0.86
  text "1.4mil" at 325.611,185.107 h0.86
  text "FR-4" at 340.92,183.879 h0.86
  text "Bottom Layer" at 288.544,182.65 h0.86
  text "(.GBL)" at 311.298,182.65 h0.86
  text "1.4mil" at 325.611,182.65 h0.86
  text "Bottom Solder Mask" at 288.544,180.192 h0.86
  text "(.GBS)" at 311.298,180.192 h0.86
  text "Solder Resist" at 340.92,180.192 h0.86
  text ".Layer_Name" at 14.656,-21.806 h1.52
M13 Component Bodies Top:
  text ".Layer_Name" at 14.656,-21.806 h1.52
M14 Component Bodies Bottom:
  text ".Layer_Name" at 14.656,-21.806 h1.52
M15 Courtyards Top:
  text ".Layer_Name" at 14.656,-21.806 h1.52
M16 Courtyards Bottom:
  text ".Layer_Name" at 14.656,-21.806 h1.52
Drill Drawing:
  text ".PRJ_Number" at 41.75,20.598 h1
  text ".legend" at 130.112,18.428 h1.52
  text "Drill Table" at 130.746,13.729 h1.52
  text ".Layer_Name" at 14.656,-21.806 h1.52

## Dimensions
0,0 to -0.5,50 on M2 Board Dimensions
40.9,-1.2 to 0,49.894 on M2 Board Dimensions
0,-10.427 to 25.4,-10.427 on M2 Board Dimensions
